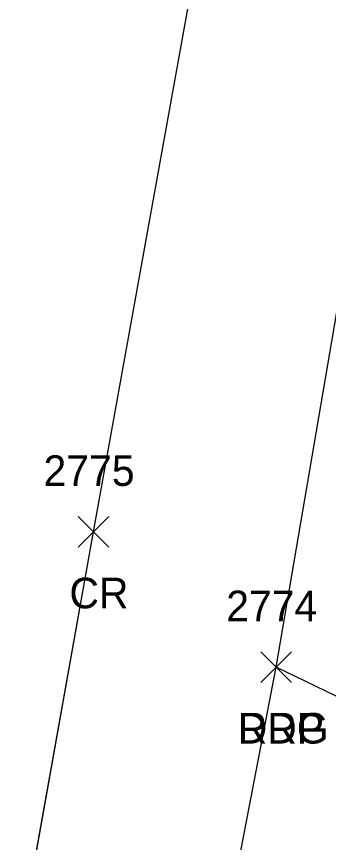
# Model space of a CAD drawing. Extents: x 1554668 to 1563881, y 831386 to 834374.
# Drawn here: x 1562231.1 to 1562251.5, y 832545.4 to 832599.4 of the extents above; entities that cross this region are included whole.
import ezdxf

# ---------------------------------------------------------------- set-up
doc = ezdxf.new("R2010")
doc.units = 0
for name, color, linetype in [('P_A', 7, 'Continuous'), ('P_I', 7, 'Continuous'), ('P_TIC', 7, 'Continuous'), ('PET', 7, 'Continuous'), ('PRC', 7, 'Continuous'), ('R_A', 7, 'Continuous'), ('R_I', 7, 'Continuous'), ('R_TIC', 7, 'Continuous'), ('RDG', 7, 'Continuous')]:
    doc.layers.add(name, color=color, linetype=linetype)

msp = doc.modelspace()

# ---------------------------------------------------------------- linework, layer by layer
at = {"layer": 'P_TIC'}
for points in [[(1562235.122, 832564.744), (1562237.122, 832566.744)], [(1562237.122, 832564.744), (1562235.122, 832566.744)], [(1562247.062, 832555.9), (1562249.062, 832557.9)], [(1562249.062, 832555.9), (1562247.062, 832557.9)]]:
    msp.add_lwpolyline(points, dxfattribs=at)
at = {"layer": 'PET'}
for points in [[(1562193.167, 832267.13), (1562201.146, 832309.703), (1562207.218, 832342.575), (1562208.538, 832349.445), (1562211.679, 832366.094), (1562212.836, 832373.113), (1562216.871, 832394.677), (1562221.784, 832421.25), (1562225.693, 832442.111), (1562233.351, 832484.078), (1562234.186, 832488.931), (1562241.957, 832528.547), (1562242.008, 832533.059), (1562244.222, 832536.962), (1562248.062, 832556.9), (1562257.295, 832610.994), (1562261.428, 832631.195), (1562266.166, 832657.988), (1562270.512, 832679.644), (1562276.163, 832714.072), (1562282.459, 832748.505), (1562288.68, 832787.056), (1562293.2, 832810.286), (1562300.396, 832850.568)], [(1562193.171, 832267.13), (1562201.149, 832309.703), (1562207.222, 832342.574), (1562208.542, 832349.444), (1562211.683, 832366.093), (1562212.84, 832373.112), (1562216.874, 832394.674), (1562221.788, 832421.249), (1562225.694, 832442.106), (1562233.354, 832484.072), (1562234.19, 832488.925), (1562241.961, 832528.547), (1562242.013, 832533.06), (1562244.225, 832536.956), (1562248.066, 832556.896), (1562257.301, 832610.991), (1562261.43, 832631.195), (1562266.171, 832657.989), (1562270.514, 832679.643), (1562276.166, 832714.07), (1562282.463, 832748.508), (1562288.682, 832787.054), (1562293.205, 832810.287), (1562300.398, 832850.573)], [(1562193.171, 832267.13), (1562201.149, 832309.703), (1562207.222, 832342.574), (1562208.542, 832349.444), (1562211.683, 832366.093), (1562212.84, 832373.112), (1562216.874, 832394.674), (1562221.788, 832421.249), (1562225.694, 832442.106), (1562233.354, 832484.072), (1562234.19, 832488.925), (1562241.961, 832528.547), (1562242.013, 832533.06), (1562244.225, 832536.956), (1562248.066, 832556.896), (1562257.301, 832610.991), (1562261.43, 832631.195), (1562266.171, 832657.989), (1562270.514, 832679.643), (1562276.166, 832714.07), (1562282.463, 832748.508), (1562288.682, 832787.054), (1562293.205, 832810.287), (1562300.398, 832850.573)], [(1562193.171, 832267.13), (1562201.149, 832309.703), (1562207.222, 832342.574), (1562208.542, 832349.444), (1562211.683, 832366.093), (1562212.84, 832373.112), (1562216.874, 832394.674), (1562221.788, 832421.249), (1562225.694, 832442.106), (1562233.354, 832484.072), (1562234.19, 832488.925), (1562241.961, 832528.547), (1562242.013, 832533.06), (1562244.225, 832536.956), (1562248.066, 832556.896), (1562257.301, 832610.991), (1562261.43, 832631.195), (1562266.171, 832657.989), (1562270.514, 832679.643), (1562276.166, 832714.07), (1562282.463, 832748.508), (1562288.682, 832787.054), (1562293.205, 832810.287), (1562300.398, 832850.573)]]:
    msp.add_lwpolyline(points, dxfattribs=at)
at = {"layer": 'PRC'}
for points in [[(1562110.411, 831900.561), (1562120.308, 831948.457), (1562125.632, 831978.446), (1562135.485, 832029.35), (1562141.594, 832061.08), (1562148.973, 832098.697), (1562154.265, 832127.132), (1562163.42, 832175.531), (1562172.445, 832223.752), (1562181.394, 832270.005), (1562188.915, 832310.797), (1562198.31, 832360.399), (1562204.785, 832396.81), (1562210.164, 832423.469), (1562217.979, 832466.497), (1562228.735, 832524.397), (1562236.126, 832565.741), (1562244.769, 832613.731), (1562253.108, 832660.756), (1562257.149, 832682.207), (1562263.128, 832717.528), (1562269.494, 832752.574), (1562275.778, 832790.076), (1562288.132, 832857.633)], [(1562110.411, 831900.561), (1562120.308, 831948.457), (1562125.632, 831978.446), (1562135.485, 832029.35), (1562141.594, 832061.08), (1562148.973, 832098.697), (1562154.265, 832127.132), (1562163.42, 832175.531), (1562172.445, 832223.752), (1562181.394, 832270.005), (1562188.915, 832310.797), (1562198.31, 832360.399), (1562204.785, 832396.81), (1562210.164, 832423.469), (1562217.979, 832466.497), (1562228.735, 832524.397), (1562236.126, 832565.741), (1562244.769, 832613.731), (1562253.108, 832660.756), (1562257.149, 832682.207), (1562263.128, 832717.528), (1562269.494, 832752.574), (1562275.778, 832790.076), (1562288.132, 832857.633)], [(1562110.411, 831900.561), (1562120.308, 831948.457), (1562125.632, 831978.446), (1562135.485, 832029.35), (1562141.594, 832061.08), (1562148.973, 832098.697), (1562154.265, 832127.132), (1562163.42, 832175.531), (1562172.445, 832223.752), (1562181.394, 832270.005), (1562188.915, 832310.797), (1562198.31, 832360.399), (1562204.785, 832396.81), (1562210.164, 832423.469), (1562217.979, 832466.497), (1562228.735, 832524.397), (1562236.126, 832565.741), (1562244.769, 832613.731), (1562253.108, 832660.756), (1562257.149, 832682.207), (1562263.128, 832717.528), (1562269.494, 832752.574), (1562275.778, 832790.076), (1562288.132, 832857.633)], [(1562110.416, 831900.563), (1562120.309, 831948.456), (1562125.634, 831978.446), (1562135.488, 832029.349), (1562141.594, 832061.08), (1562148.971, 832098.698), (1562154.265, 832127.137), (1562163.419, 832175.534), (1562172.445, 832223.751), (1562181.389, 832270.011), (1562188.91, 832310.801), (1562198.306, 832360.397), (1562204.781, 832396.813), (1562210.163, 832423.475), (1562217.975, 832466.5), (1562228.731, 832524.404), (1562236.122, 832565.744), (1562244.766, 832613.73), (1562253.104, 832660.756), (1562257.145, 832682.206), (1562263.124, 832717.525), (1562269.49, 832752.57), (1562275.776, 832790.077), (1562288.125, 832857.632)]]:
    msp.add_lwpolyline(points, dxfattribs=at)
at = {"layer": 'R_TIC'}
for points in [[(1562247.062, 832555.9), (1562249.062, 832557.9)], [(1562249.062, 832555.9), (1562247.062, 832557.9)]]:
    msp.add_lwpolyline(points, dxfattribs=at)
at = {"layer": 'RDG'}
for points in [[(1562303.974, 832553.705), (1562296.214, 832550.576), (1562283.948, 832548.194), (1562269.877, 832550.821), (1562257.074, 832552.545), (1562248.062, 832556.9)], [(1562303.978, 832553.702), (1562296.215, 832550.57), (1562283.95, 832548.189), (1562269.881, 832550.821), (1562257.078, 832552.543), (1562248.066, 832556.896)], [(1562303.978, 832553.702), (1562296.215, 832550.57), (1562283.95, 832548.189), (1562269.881, 832550.821), (1562257.078, 832552.543), (1562248.066, 832556.896)], [(1562303.978, 832553.702), (1562296.215, 832550.57), (1562283.95, 832548.189), (1562269.881, 832550.821), (1562257.078, 832552.543), (1562248.066, 832556.896)]]:
    msp.add_lwpolyline(points, dxfattribs=at)

# ---------------------------------------------------------------- texts
at = {"layer": 'P_A'}
for s, p in [('CR', (1562234.555, 832560.744)), ('RDP', (1562245.55, 832551.9))]:
    msp.add_text(s, height=2, dxfattribs=at).set_placement(p)
at = {"layer": 'P_I'}
for s, p in [('2775', (1562232.863, 832568.744)), ('2774', (1562244.802, 832559.9))]:
    msp.add_text(s, height=2, dxfattribs=at).set_placement(p)
at = {"layer": 'R_A'}
msp.add_text('DRG', height=2, dxfattribs=at).set_placement((1562245.55, 832551.9))
at = {"layer": 'R_I'}
msp.add_text('2774', height=2, dxfattribs=at).set_placement((1562244.802, 832559.9))

doc.saveas('drawing.dxf')
